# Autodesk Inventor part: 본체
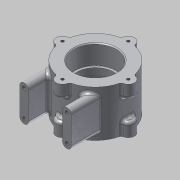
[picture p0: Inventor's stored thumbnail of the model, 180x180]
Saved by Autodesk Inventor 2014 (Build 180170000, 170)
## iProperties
Created: 2015-03
Part Number: 본체
Material: 알루미늄 6061
Document SubType Name: Modeling
Designer: MYHOME
Density: 2.71 g/cm^3
Appearance: 알루미늄 - 평지
Mass: 450.776 g
Surface Area: 332.745 cm^2
Volume: 166.338 cm^3
Author: MYHOME
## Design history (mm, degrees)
sketch "스케치1"
  geometry: C1 r 37 at (0, 0); 1 further point
  constraints: 1 centre point, 1 coincident
  dimensions: "d0" = 74 diameter of C1
extrude "돌출1" new body sketch "스케치1" stored distance "d1" = 22; taper "d2" = 0 deg
sketch "스케치2" dims "d3" = 74
  geometry: C1 r 7 at (0, 37); C2 r 7 at (37, 0); C3 r 7 at (0, -37); C4 r 7 at (-37, 0); A1 r 37 centre (0, 0) between (0, 37) and (0, -37) reference; 1 further point
  constraints: 4 centre point, 3 horizontal alignment, 3 point on circle, 2 vertical alignment, 1 coincident, 2 other
  dimensions: "d4" = 14 diameter of C2; "d5" = 14 diameter of C3; "d6" = 14 diameter of C4; "d7" = 14 diameter of C1
extrude "돌출2" join sketch "스케치2" distance "d8" = 15; taper "d9" = 0 deg
sketch "스케치3"
  geometry: A1 r 7 centre (37, 0) between (36.338, -6.969) and (36.338, 6.969) reference; A2 r 7 centre (0, 37) between (6.969, 36.338) and (-6.969, 36.338) reference; A3 r 7 centre (-37, 0) between (-36.338, 6.969) and (-36.338, -6.969) reference; A4 r 7 centre (0, -37) between (-6.969, -36.338) and (6.969, -36.338) reference; 4 further points
  constraints: 4 coincident
hole "구멍1" sketch "스케치3" at (-37, 0), (0, 37), (37, 0), (0, -37) diameter "d10" = 3.242; stored, may be unused: countersink angle "d14" = 90 deg, drill point angle "d16" = 118 deg; dims "d11" = 8, "d12" = 4, "d13" = 2, "d15" = 11
sketch "스케치4"
  geometry: C1 r 23.5 at (0, 37); A1 r 37 centre (0, 37) between (-6.969, 73.338) and (-36.338, 43.969) reference
  constraints: 1 centre point, 1 coincident
  dimensions: "d17" = 47 diameter of C1
extrude "돌출3" cut sketch "스케치4" distance "d18" = 22; taper "d19" = 0 deg
hole "구멍2" diameter "d22" = 42; stored, may be unused: countersink angle "d26" = 90 deg, drill point angle "d28" = 0 deg; dims "d20" = 10, "d21" = 10, "d23" = 6, "d24" = 47, "d25" = 22, "d27" = 30
sketch "스케치5"
  geometry: L1 (-29, -17)-(-19, -17); L2 (-19, -17)-(-19, -56); L3 (-19, -56)-(-29, -56); L4 (-29, -56)-(-29, -17); L5 (19, -18.4)-(29, -18.4); L6 (29, -18.4)-(29, -56); L7 (29, -56)-(19, -56); L8 (19, -56)-(19, -18.4); L9 (0, 0)-(0, -56); A1 r 37 centre (0, 0) between (-36.338, -6.969) and (-6.969, -36.338) reference; A2 r 37 centre (0, 0) between (6.969, -36.338) and (36.338, -6.969) reference; 1 further point
  constraints: 18 end point, 5 parallel, 2 horizontal, 2 perpendicular, 1 collinear, 1 other
  dimensions: "d29" = 10 distance of L2.end L3.end; "d30" = 10 distance of L6.end L7.end; "d31" = 56 distance from line of L3 point (0, 0); "d32" = 58 distance between parallel lines of L6 L4; "d33" = 39.00001 distance of L3.end L1.start; "d34" = 37.60001 distance of L5.end L6.end; "d35" = 56 distance of L9.start L9.end
extrude "돌출4" join sketch "스케치5" stored distance "d36" = 40; taper "d37" = 0 deg
chamfer "모따기1" distance "d38" = 1; stored, may be unused: second distance "d39" = 2, angle "d40" = 45 deg
fillet "모깎기1" dims "d41" = 0.3
fillet "모깎기2" dims "d42" = 5
sketch "스케치6"
  geometry: L1 (53, 30)-(53, 0) reference; L2 (43, 30)-(43, 0) reference; A1 r 5 centre (0, 0) between (-5, 0) and (5, 0) reference; A2 r 5 centre (0, 30) between (5, 30) and (-5, 30) reference; A3 r 5 centre (48, 0) between (43, 0) and (53, 0) reference; A4 r 5 centre (48, 30) between (53, 30) and (43, 30) reference; 5 further points
  constraints: 4 coincident
hole "구멍3" sketch "스케치6" at (0, 30), (0, 0), (48, 0), (48, 30) diameter "d43" = 4.134; stored, may be unused: countersink angle "d47" = 90 deg, drill point angle "d49" = 118 deg; dims "d44" = 6, "d45" = 47, "d46" = 22, "d48" = 8
fillet "모깎기3" dims "d50" = 3
fillet "모깎기4" dims "d51" = 3
fillet "모깎기5" dims "d52" = 3
sketch "스케치7"
  geometry: L1 (0, 0)-(-21, 0); L2 (0, 0)-(-26.163, 26.163); A1 r 37 centre (0, 0) between (-9.104, 35.863) and (-35.863, 9.104) reference; 2 further points
  constraints: 4 end point, 1 coincident, 1 horizontal, 1 horizontal alignment, 1 point on circle, 1 other
node "작업 평면1"
sketch "스케치8"
  geometry: L1 (18.921, -26)-(-18.921, -26) reference; 2 further points
  constraints: 1 coincident, 1 other
  dimensions: "d53" = 26 distance from line of L1 point (0, 0)
feature "엠보싱1" sketch "스케치8" dims "d54" = 0.5, "d55" = 0
node "솔리드1"
mirror "대칭1"
node "투영된 루프1"
